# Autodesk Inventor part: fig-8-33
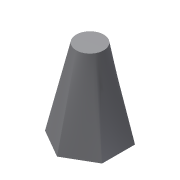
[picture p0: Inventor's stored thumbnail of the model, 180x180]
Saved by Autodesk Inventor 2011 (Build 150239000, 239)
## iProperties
Created: 2007-05
Part Number: fig-8-33
Document SubType Name: Modeling
Designer: Administrator
Density: 1 g/cm^3
Author: Administrator
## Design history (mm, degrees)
sketch "Sketch1"
  geometry: L1 (0, 30)-(25.981, 15); L2 (25.981, 15)-(25.981, -15); L3 (25.981, -15)-(0, -30); L4 (0, -30)-(-25.981, -15); L5 (-25.981, -15)-(-25.981, 15); L6 (-25.981, 15)-(0, 30); 2 further points
  constraints: 12 end point, 1 coincident, 1 vertical, 14 other
workplane "Work Plane1"
sketch "Sketch2"
  geometry: C1 r 12.5 at (0, 0)
  constraints: 1 centre point, 1 other
sketch "Sketch3"
  geometry: L1 (0, 0)-(0, 75)
  constraints: 2 end point, 1 vertical, 1 other
loft "Loft1" dims "d5" = 0, "d6" = 90 deg, "d7" = 0, "d8" = 90 deg
body "Solid1"
other parameters: "d1" = 75
